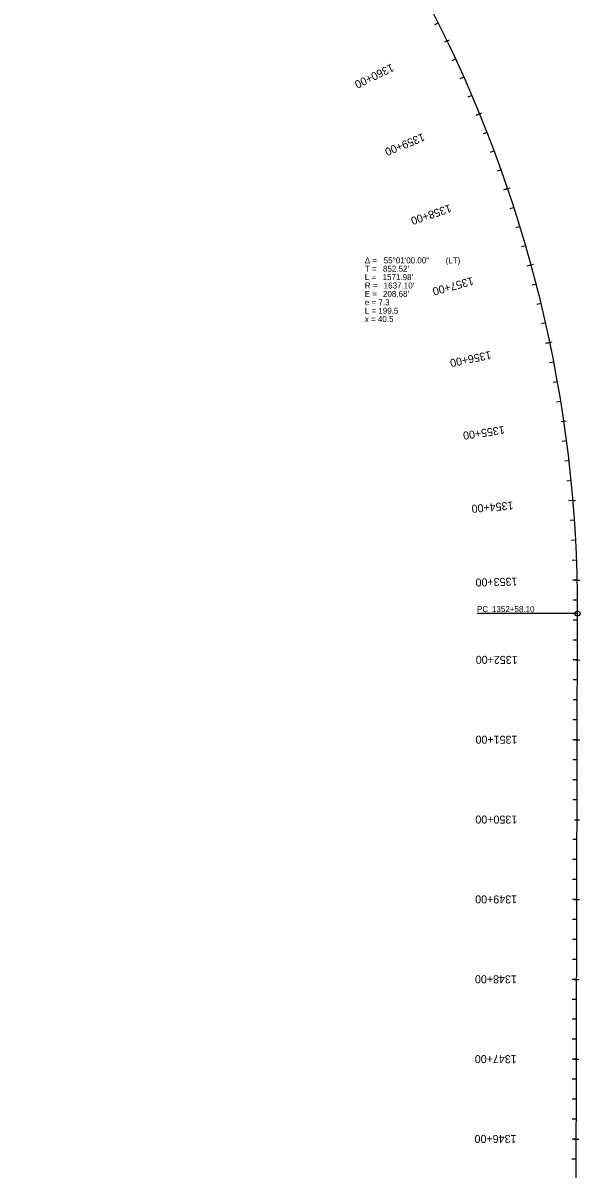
# Model space of a CAD drawing. Extents: x 14541681 to 14544384, y 8572153 to 8583558.
# Drawn here: x 14543569 to 14544267, y 8576421 to 8577856 of the extents above; entities that cross this region are included whole.
import ezdxf

# ---------------------------------------------------------------- set-up
doc = ezdxf.new("R2010")
doc.units = 0
for name, color, linetype in [('Alignment', 7, 'Continuous'), ('TextAlignment', 7, 'Continuous'), ('TextAlignmentLrg', 7, 'Continuous'), ('TextAlignmentSml', 7, 'Continuous')]:
    doc.layers.add(name, color=color, linetype=linetype)

msp = doc.modelspace()

# ---------------------------------------------------------------- linework, layer by layer
at = {"layer": 'Alignment'}
msp.add_line((14544251.8, 8572158.2), (14544263.9, 8577116.3), dxfattribs=at)
msp.add_arc((14542626.8, 8577120.2), 1637.1, 359.8604, 54.877, dxfattribs=at)
at = {"layer": 'TextAlignment'}
for p in [(14544263.9, 8577116.3), (14544137.9, 8577116.6)]:
    msp.add_line(p, (14544137.9, 8577116.6), dxfattribs=at)
msp.add_circle((14544263.9, 8577116.3), 3.12, dxfattribs=at)
at = {"layer": 'TextAlignmentLrg'}
for p, q in [((14544097.7, 8577832.1), (14544103.2, 8577834.8)), ((14544141.2, 8577742.1), (14544136.2, 8577740.1)), ((14544176.3, 8577648.5), (14544171.2, 8577646.8)), ((14544205.7, 8577552.9), (14544200.4, 8577551.5)), ((14544229.2, 8577455.8), (14544223.8, 8577454.6)), ((14544243.6, 8577356.9), (14544249.7, 8577357.8)), ((14544258.1, 8577258), (14544252.7, 8577257.5)), ((14544263.5, 8577158.1), (14544258, 8577158)), ((14544263.8, 8577058.2), (14544258.3, 8577058.2)), ((14544263.5, 8576958.2), (14544258.1, 8576958.2)), ((14544260.2, 8576858.2), (14544266.3, 8576858.1)), ((14544263, 8576758.2), (14544257.6, 8576758.2)), ((14544262.8, 8576658.2), (14544257.3, 8576658.2)), ((14544262.6, 8576558.2), (14544257.1, 8576558.2)), ((14544262.3, 8576458.2), (14544256.9, 8576458.2))]:
    msp.add_line(p, q, dxfattribs=at)
at = {"layer": 'TextAlignmentSml'}
for p, q in [((14544089.4, 8577855.8), (14544084.5, 8577853.4)), ((14544097.7, 8577832.1), (14544103.2, 8577834.8)), ((14544111.1, 8577810.8), (14544106.2, 8577808.5)), ((14544121.5, 8577788.1), (14544116.5, 8577785.9)), ((14544131.5, 8577765.2), (14544126.5, 8577763)), ((14544138.4, 8577741), (14544144, 8577743.3)), ((14544150.5, 8577718.9), (14544145.4, 8577716.9)), ((14544159.5, 8577695.6), (14544154.4, 8577693.7)), ((14544168.1, 8577672.1), (14544163, 8577670.3)), ((14544173.4, 8577647.5), (14544179.2, 8577649.5)), ((14544184.2, 8577624.8), (14544179, 8577623.1)), ((14544191.8, 8577601), (14544186.5, 8577599.4)), ((14544198.9, 8577577), (14544193.7, 8577575.5)), ((14544202.8, 8577552.1), (14544208.7, 8577553.8)), ((14544212.1, 8577528.8), (14544206.8, 8577527.4)), ((14544218.2, 8577504.5), (14544212.9, 8577503.3)), ((14544223.9, 8577480.2), (14544218.5, 8577479)), ((14544226.2, 8577455.1), (14544232.2, 8577456.4)), ((14544234.1, 8577431.3), (14544228.7, 8577430.2)), ((14544238.7, 8577406.7), (14544233.3, 8577405.7)), ((14544242.9, 8577382), (14544237.5, 8577381.2)), ((14544243.6, 8577356.9), (14544249.7, 8577357.8)), ((14544250.1, 8577332.6), (14544244.7, 8577331.8)), ((14544253.1, 8577307.7), (14544247.7, 8577307.1)), ((14544255.8, 8577282.9), (14544250.4, 8577282.3)), ((14544255.1, 8577257.7), (14544261.2, 8577258.2)), ((14544260, 8577233.1), (14544254.6, 8577232.7)), ((14544261.6, 8577208.1), (14544256.1, 8577207.8)), ((14544262.7, 8577183.1), (14544257.3, 8577182.9)), ((14544260.4, 8577158.1), (14544266.5, 8577158.2)), ((14544263.9, 8577133.2), (14544258.4, 8577133.1)), ((14544263.9, 8577108.2), (14544258.4, 8577108.2)), ((14544263.8, 8577083.2), (14544258.4, 8577083.2)), ((14544260.7, 8577058.2), (14544266.8, 8577058.1)), ((14544263.7, 8577033.2), (14544258.3, 8577033.2)), ((14544263.7, 8577008.2), (14544258.2, 8577008.2)), ((14544263.6, 8576983.2), (14544258.1, 8576983.2)), ((14544260.5, 8576958.2), (14544266.6, 8576958.1)), ((14544263.5, 8576933.2), (14544258, 8576933.2)), ((14544263.4, 8576908.2), (14544257.9, 8576908.2)), ((14544263.3, 8576883.2), (14544257.9, 8576883.2)), ((14544260.2, 8576858.2), (14544266.3, 8576858.1)), ((14544263.2, 8576833.2), (14544257.8, 8576833.2)), ((14544263.2, 8576808.2), (14544257.7, 8576808.2)), ((14544263.1, 8576783.2), (14544257.6, 8576783.2)), ((14544260, 8576758.2), (14544266.1, 8576758.1)), ((14544263, 8576733.2), (14544257.5, 8576733.2)), ((14544262.9, 8576708.2), (14544257.5, 8576708.2)), ((14544262.9, 8576683.2), (14544257.4, 8576683.2)), ((14544259.7, 8576658.2), (14544265.9, 8576658.1)), ((14544262.7, 8576633.2), (14544257.3, 8576633.2)), ((14544262.7, 8576608.2), (14544257.2, 8576608.2)), ((14544262.6, 8576583.2), (14544257.2, 8576583.2)), ((14544259.5, 8576558.2), (14544265.6, 8576558.1)), ((14544262.5, 8576533.2), (14544257, 8576533.2)), ((14544262.4, 8576508.2), (14544257, 8576508.2)), ((14544262.4, 8576483.2), (14544256.9, 8576483.2)), ((14544259.3, 8576458.2), (14544265.4, 8576458.1)), ((14544262.3, 8576433.2), (14544256.8, 8576433.2))]:
    msp.add_line(p, q, dxfattribs=at)

# ---------------------------------------------------------------- texts
at = {"layer": 'TextAlignment'}
for s, p in [('Δ = ', (14543997.2, 8577554.9)), ('55°01\'00.00"', (14544020.9, 8577554.9)), (' (LT)', (14544095.8, 8577554.9)), ('T = ', (14543997.2, 8577544.4)), ('L = ', (14543997.2, 8577533.9)), ("1571.98'", (14544019.5, 8577533.9)), ("852.52'", (14544020, 8577544.4)), ('R = ', (14543997.2, 8577523.4)), ("1637.10'", (14544020.9, 8577523.4)), ('e = 7.3', (14543997.2, 8577502.4)), ('E = ', (14543997.2, 8577512.9)), ("208.68'", (14544020, 8577512.9)), ('L = 199.5', (14543997.2, 8577491.9)), ('x = 40.5', (14543997.2, 8577481.4))]:
    msp.add_text(s, height=7.5, dxfattribs=at).set_placement(p)
for s, p in [('PC', (14544137.9, 8577118.2)), ('1352+58.10', (14544156.6, 8577118.2))]:
    msp.add_text(s, height=7.5, rotation=359.8604, dxfattribs=at).set_placement(p)
at = {"layer": 'TextAlignmentLrg'}
for s, rotation, p in [('1360+00', 205.8256, (14544030.7, 8577805.3)), ('1355+00', 188.3264, (14544171.7, 8577351.4)), ('1350+00', 179.8604, (14544188.3, 8576863.3))]:
    msp.add_text(s, height=10.02, rotation=rotation, dxfattribs=at).set_placement(p)
at = {"layer": 'TextAlignmentSml'}
for s, rotation, p in [('1360+00', 205.8256, (14544030.7, 8577805.3)), ('1359+00', 202.3258, (14544069.9, 8577718.3)), ('1358+00', 198.8259, (14544103.7, 8577629.1)), ('1357+00', 195.3261, (14544132, 8577538)), ('1356+00', 191.8263, (14544154.7, 8577445.3)), ('1355+00', 188.3264, (14544171.7, 8577351.4)), ('1354+00', 184.8266, (14544183, 8577256.7)), ('1353+00', 181.3268, (14544188.4, 8577161.4)), ('1352+00', 179.8604, (14544188.8, 8577063.3)), ('1351+00', 179.8604, (14544188.5, 8576963.3)), ('1350+00', 179.8604, (14544188.3, 8576863.3)), ('1349+00', 179.8604, (14544188.1, 8576763.3)), ('1348+00', 179.8604, (14544187.8, 8576663.3)), ('1347+00', 179.8604, (14544187.6, 8576563.3)), ('1346+00', 179.8604, (14544187.3, 8576463.3))]:
    msp.add_text(s, height=10.02, rotation=rotation, dxfattribs=at).set_placement(p)

doc.saveas('drawing.dxf')
